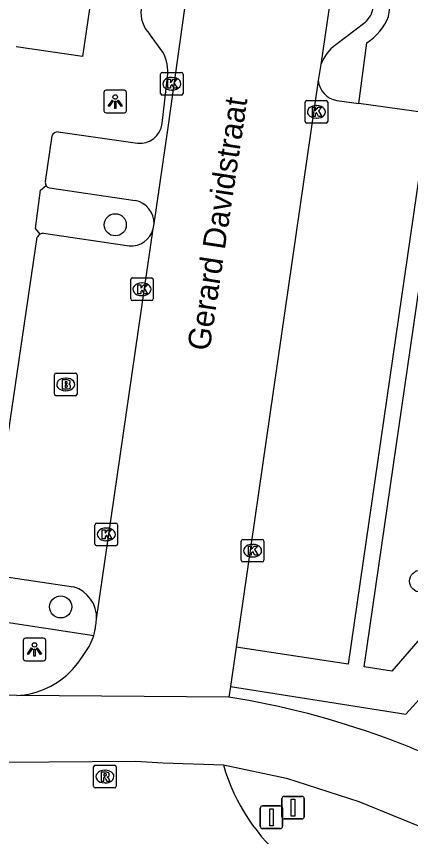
# Model space of a CAD drawing. Extents: x 163686 to 164493, y 382719 to 383870.
# Drawn here: x 163896.14 to 163913.6, y 382940.91 to 382977.2 of the extents above; entities that cross this region are included whole.
import ezdxf

# ---------------------------------------------------------------- set-up
doc = ezdxf.new("R2010")
doc.units = 0
for name, color, linetype in [('IMGEO_Boom', 7, 'Continuous'), ('IMGEO_Brandkraan', 7, 'Continuous'), ('IMGEO_Fietspad_gesloten', 7, 'Continuous'), ('IMGEO_Kolk', 7, 'Continuous'), ('IMGEO_Lichtpunt', 7, 'Continuous'), ('IMGEO_Openbare_ruimte_label', 7, 'Continuous'), ('IMGEO_Parkeervlak_open', 7, 'Continuous'), ('IMGEO_Rijbaan_lokaal_gesloten', 7, 'Continuous'), ('IMGEO_Rijbaan_lokaal_open', 7, 'Continuous'), ('IMGEO_Rioolput', 7, 'Continuous'), ('IMGEO_Verkeersbordpaal', 7, 'Continuous'), ('IMGEO_Voetpad_open', 7, 'Continuous')]:
    doc.layers.add(name, color=color, linetype=linetype)

msp = doc.modelspace()

# ---------------------------------------------------------------- linework, layer by layer
at = {"layer": 'IMGEO_Boom'}
for centre in [(163900.52, 382967.982), (163914.042, 382952.215), (163898.102, 382951.077)]:
    msp.add_circle(centre, 0.489, dxfattribs=at)
at = {"layer": 'IMGEO_Brandkraan'}
for p, q in [((163897.901, 382961.419), (163898.753, 382961.419)), ((163897.826, 382960.493), (163897.826, 382961.345)), ((163898.314, 382961.199), (163898.339, 382961.199)), ((163898.827, 382961.345), (163898.827, 382960.493)), ((163898.753, 382960.419), (163897.901, 382960.419)), ((163898.337, 382960.639), (163898.312, 382960.639))]:
    msp.add_line(p, q, dxfattribs=at)
for points in [[(163897.901, 382961.419), (163898.753, 382961.419)], [(163897.826, 382960.493), (163897.826, 382961.345)], [(163898.174, 382961.119), (163898.174, 382960.719), (163898.387, 382960.719)], [(163898.405, 382961.119), (163898.174, 382961.119)], [(163898.353, 382961.038), (163898.299, 382961.038), (163898.299, 382960.962)], [(163898.827, 382961.345), (163898.827, 382960.493)], [(163898.299, 382960.962), (163898.352, 382960.962)], [(163898.361, 382960.886), (163898.299, 382960.886), (163898.299, 382960.805)], [(163898.299, 382960.805), (163898.361, 382960.805)], [(163898.753, 382960.419), (163897.901, 382960.419)]]:
    msp.add_lwpolyline(points, dxfattribs=at)
for centre, radius, start, end in [((163897.903, 382961.343), 0.0765, 91.552, 178.448), ((163897.903, 382961.343), 0.0765, 91.552, 178.448), ((163898.751, 382961.343), 0.0765, 1.552, 88.448), ((163898.751, 382961.343), 0.0765, 1.552, 88.448), ((163898.354, 382961), 0.0379, 267.8285, 90.9355), ((163898.409, 382960.974), 0.145, 59.4692, 91.5367), ((163898.434, 382961.021), 0.0922, 285.5137, 58.1501), ((163898.362, 382960.845), 0.0404, 269.8759, 90.5077), ((163898.393, 382960.97), 0.251, 268.6676, 293.5347), ((163898.439, 382960.829), 0.105, 301.3115, 78.989), ((163897.903, 382960.495), 0.0765, 181.552, 268.448), ((163897.903, 382960.495), 0.0765, 181.552, 268.448), ((163898.751, 382960.495), 0.0765, 271.552, 358.448), ((163898.751, 382960.495), 0.0765, 271.552, 358.448)]:
    msp.add_arc(centre, radius, start, end, dxfattribs=at)
for centre, major_axis, ratio, start_param, end_param in [((163898.313, 382960.919), (-0.387, 0.002), 0.722429, 4.712389, 7.853982), ((163898.338, 382960.919), (-0.39, 0.002), 0.717154, 1.570796, 4.712389)]:
    msp.add_ellipse(centre, major_axis=major_axis, ratio=ratio, start_param=start_param, end_param=end_param, dxfattribs=at)
at = {"layer": 'IMGEO_Fietspad_gesloten'}
for points in [[(163896.153, 382947.159), (163892.166, 382947.287)], [(163905.31, 382944.094), (163908.103, 382943.494), (163911.308, 382942.464), (163918.914, 382939.372), (163922.003, 382938.314), (163925.083, 382937.398), (163927.264, 382936.845)]]:
    msp.add_lwpolyline(points, dxfattribs=at)
for centre, radius, start, end in [((163899.796, 382910.658), 36.873, 69.9359, 81.0113), ((163900.117, 382911.449), 36.02, 65.7637, 69.9836)]:
    msp.add_arc(centre, radius, start, end, dxfattribs=at)
at = {"layer": 'IMGEO_Kolk'}
for p, q in [((163902.526, 382973.797), (163902.526, 382974.649)), ((163902.601, 382974.723), (163903.453, 382974.723)), ((163903.014, 382974.503), (163903.039, 382974.503)), ((163903.527, 382974.649), (163903.527, 382973.797)), ((163903.453, 382973.723), (163902.601, 382973.723)), ((163903.037, 382973.943), (163903.012, 382973.943)), ((163908.929, 382972.555), (163908.929, 382973.407)), ((163909.004, 382973.481), (163909.856, 382973.481)), ((163909.93, 382973.407), (163909.93, 382972.555)), ((163909.417, 382973.261), (163909.442, 382973.261)), ((163909.44, 382972.701), (163909.415, 382972.701)), ((163909.856, 382972.481), (163909.004, 382972.481)), ((163901.204, 382964.705), (163901.204, 382965.557)), ((163901.279, 382965.631), (163902.131, 382965.631)), ((163901.692, 382965.411), (163901.717, 382965.411)), ((163902.205, 382965.557), (163902.205, 382964.705)), ((163901.715, 382964.851), (163901.69, 382964.851)), ((163902.131, 382964.631), (163901.279, 382964.631)), ((163899.622, 382953.859), (163899.622, 382954.711)), ((163899.697, 382954.785), (163900.549, 382954.785)), ((163900.11, 382954.565), (163900.135, 382954.565)), ((163900.623, 382954.711), (163900.623, 382953.859)), ((163900.549, 382953.785), (163899.697, 382953.785)), ((163900.133, 382954.005), (163900.108, 382954.005)), ((163906.102, 382953.138), (163906.102, 382953.99)), ((163906.177, 382954.064), (163907.029, 382954.064)), ((163906.59, 382953.844), (163906.615, 382953.844)), ((163907.103, 382953.99), (163907.103, 382953.138)), ((163907.029, 382953.064), (163906.177, 382953.064)), ((163906.613, 382953.284), (163906.588, 382953.284))]:
    msp.add_line(p, q, dxfattribs=at)
for points in [[(163902.526, 382973.797), (163902.526, 382974.649)], [(163902.601, 382974.723), (163903.453, 382974.723)], [(163903.527, 382974.649), (163903.527, 382973.797)], [(163902.847, 382974.423), (163902.97, 382974.423), (163902.97, 382974.272), (163903.1, 382974.423), (163903.264, 382974.423), (163903.118, 382974.272), (163903.271, 382974.023), (163903.119, 382974.023), (163903.034, 382974.187), (163902.97, 382974.12), (163902.97, 382974.023), (163902.847, 382974.023), (163902.847, 382974.423)], [(163903.453, 382973.723), (163902.601, 382973.723)], [(163908.929, 382972.555), (163908.929, 382973.407)], [(163909.004, 382973.481), (163909.856, 382973.481)], [(163909.93, 382973.407), (163909.93, 382972.555)], [(163909.25, 382973.181), (163909.373, 382973.181), (163909.373, 382973.03), (163909.503, 382973.181), (163909.667, 382973.181), (163909.521, 382973.03), (163909.674, 382972.781), (163909.522, 382972.781), (163909.437, 382972.945), (163909.373, 382972.878), (163909.373, 382972.781), (163909.25, 382972.781), (163909.25, 382973.181)], [(163909.856, 382972.481), (163909.004, 382972.481)], [(163901.204, 382964.705), (163901.204, 382965.557)], [(163901.279, 382965.631), (163902.131, 382965.631)], [(163902.205, 382965.557), (163902.205, 382964.705)], [(163901.525, 382965.331), (163901.648, 382965.331), (163901.648, 382965.18), (163901.778, 382965.331), (163901.942, 382965.331), (163901.796, 382965.18), (163901.949, 382964.931), (163901.797, 382964.931), (163901.712, 382965.095), (163901.648, 382965.028), (163901.648, 382964.931), (163901.525, 382964.931), (163901.525, 382965.331)], [(163902.131, 382964.631), (163901.279, 382964.631)], [(163899.622, 382953.859), (163899.622, 382954.711)], [(163899.697, 382954.785), (163900.549, 382954.785)], [(163899.943, 382954.485), (163900.066, 382954.485), (163900.066, 382954.334), (163900.196, 382954.485), (163900.36, 382954.485), (163900.214, 382954.334), (163900.367, 382954.085), (163900.215, 382954.085), (163900.13, 382954.249), (163900.066, 382954.182), (163900.066, 382954.085), (163899.943, 382954.085), (163899.943, 382954.485)], [(163900.623, 382954.711), (163900.623, 382953.859)], [(163900.549, 382953.785), (163899.697, 382953.785)], [(163906.102, 382953.138), (163906.102, 382953.99)], [(163906.177, 382954.064), (163907.029, 382954.064)], [(163906.423, 382953.764), (163906.546, 382953.764), (163906.546, 382953.613), (163906.676, 382953.764), (163906.84, 382953.764), (163906.694, 382953.613), (163906.847, 382953.364), (163906.695, 382953.364), (163906.61, 382953.528), (163906.546, 382953.461), (163906.546, 382953.364), (163906.423, 382953.364), (163906.423, 382953.764)], [(163907.103, 382953.99), (163907.103, 382953.138)], [(163907.029, 382953.064), (163906.177, 382953.064)]]:
    msp.add_lwpolyline(points, dxfattribs=at)
for centre, start, end in [((163902.603, 382974.647), 91.552, 178.448), ((163902.603, 382974.647), 91.552, 178.448), ((163903.451, 382974.647), 1.552, 88.448), ((163903.451, 382974.647), 1.552, 88.448), ((163902.603, 382973.799), 181.552, 268.448), ((163902.603, 382973.799), 181.552, 268.448), ((163903.451, 382973.799), 271.552, 358.448), ((163903.451, 382973.799), 271.552, 358.448), ((163909.006, 382973.405), 91.552, 178.448), ((163909.006, 382973.405), 91.552, 178.448), ((163909.854, 382973.405), 1.552, 88.448), ((163909.854, 382973.405), 1.552, 88.448), ((163909.006, 382972.557), 181.552, 268.448), ((163909.006, 382972.557), 181.552, 268.448), ((163909.854, 382972.557), 271.552, 358.448), ((163909.854, 382972.557), 271.552, 358.448), ((163901.281, 382965.555), 91.552, 178.448), ((163901.281, 382965.555), 91.552, 178.448), ((163902.129, 382965.555), 1.552, 88.448), ((163902.129, 382965.555), 1.552, 88.448), ((163901.281, 382964.707), 181.552, 268.448), ((163901.281, 382964.707), 181.552, 268.448), ((163902.129, 382964.707), 271.552, 358.448), ((163902.129, 382964.707), 271.552, 358.448), ((163899.699, 382954.709), 91.552, 178.448), ((163899.699, 382954.709), 91.552, 178.448), ((163900.547, 382954.709), 1.552, 88.448), ((163900.547, 382954.709), 1.552, 88.448), ((163899.699, 382953.861), 181.552, 268.448), ((163899.699, 382953.861), 181.552, 268.448), ((163900.547, 382953.861), 271.552, 358.448), ((163900.547, 382953.861), 271.552, 358.448), ((163906.179, 382953.988), 91.552, 178.448), ((163906.179, 382953.988), 91.552, 178.448), ((163907.027, 382953.988), 1.552, 88.448), ((163907.027, 382953.988), 1.552, 88.448), ((163906.179, 382953.14), 181.552, 268.448), ((163906.179, 382953.14), 181.552, 268.448), ((163907.027, 382953.14), 271.552, 358.448), ((163907.027, 382953.14), 271.552, 358.448)]:
    msp.add_arc(centre, 0.0765, start, end, dxfattribs=at)
for centre, major_axis, ratio, start_param, end_param in [((163903.013, 382974.223), (-0.387, 0.002), 0.722429, 4.712389, 7.853982), ((163903.038, 382974.223), (-0.39, 0.002), 0.717154, 1.570796, 4.712389), ((163909.416, 382972.981), (-0.387, 0.002), 0.722429, 4.712389, 7.853982), ((163909.441, 382972.981), (-0.39, 0.002), 0.717154, 1.570796, 4.712389), ((163901.691, 382965.131), (-0.387, 0.002), 0.722429, 4.712389, 7.853982), ((163901.716, 382965.131), (-0.39, 0.002), 0.717154, 1.570796, 4.712389), ((163900.109, 382954.285), (-0.387, 0.002), 0.722429, 4.712389, 7.853982), ((163900.134, 382954.285), (-0.39, 0.002), 0.717154, 1.570796, 4.712389), ((163906.589, 382953.564), (-0.387, 0.002), 0.722429, 4.712389, 7.853982), ((163906.614, 382953.564), (-0.39, 0.002), 0.717154, 1.570796, 4.712389)]:
    msp.add_ellipse(centre, major_axis=major_axis, ratio=ratio, start_param=start_param, end_param=end_param, dxfattribs=at)
at = {"layer": 'IMGEO_Lichtpunt'}
for p, q in [((163900.02, 382973.839), (163900.02, 382973.032)), ((163900.02, 382973.839), (163900.02, 382973.032)), ((163900.922, 382973.934), (163900.114, 382973.934)), ((163900.922, 382973.934), (163900.114, 382973.934)), ((163901.016, 382973.032), (163901.016, 382973.839)), ((163901.016, 382973.032), (163901.016, 382973.839)), ((163900.114, 382972.938), (163900.922, 382972.938)), ((163900.114, 382972.938), (163900.922, 382972.938)), ((163896.443, 382949.596), (163896.443, 382948.789)), ((163896.443, 382949.596), (163896.443, 382948.789)), ((163897.345, 382949.691), (163896.537, 382949.691)), ((163897.345, 382949.691), (163896.537, 382949.691)), ((163897.439, 382948.789), (163897.439, 382949.596)), ((163897.439, 382948.789), (163897.439, 382949.596)), ((163896.537, 382948.695), (163897.345, 382948.695)), ((163896.537, 382948.695), (163897.345, 382948.695))]:
    msp.add_line(p, q, dxfattribs=at)
for points in [[(163900.394, 382973.503), (163900.433, 382973.475), (163900.245, 382973.213), (163900.207, 382973.24), (163900.394, 382973.503)], [(163900.496, 382973.455), (163900.543, 382973.455), (163900.543, 382973.133), (163900.496, 382973.133), (163900.496, 382973.455)], [(163900.606, 382973.475), (163900.644, 382973.502), (163900.831, 382973.24), (163900.792, 382973.212), (163900.606, 382973.475)], [(163896.817, 382949.26), (163896.856, 382949.232), (163896.668, 382948.97), (163896.63, 382948.997), (163896.817, 382949.26)], [(163896.919, 382949.212), (163896.966, 382949.212), (163896.966, 382948.89), (163896.919, 382948.89), (163896.919, 382949.212)], [(163897.029, 382949.232), (163897.067, 382949.259), (163897.254, 382948.997), (163897.215, 382948.969), (163897.029, 382949.232)]]:
    msp.add_lwpolyline(points, dxfattribs=at)
for centre in [(163900.519, 382973.637), (163896.942, 382949.394)]:
    msp.add_circle(centre, 0.0994, dxfattribs=at)
for centre, start, end in [((163900.114, 382973.839), 90, 180), ((163900.114, 382973.839), 90, 180), ((163900.922, 382973.839), 0, 90), ((163900.922, 382973.839), 0, 90), ((163900.114, 382973.032), 180, 270), ((163900.114, 382973.032), 180, 270), ((163900.922, 382973.032), 270, 0), ((163900.922, 382973.032), 270, 360), ((163896.537, 382949.596), 90, 180), ((163896.537, 382949.596), 90, 180), ((163897.345, 382949.596), 0, 90), ((163897.345, 382949.596), 0, 90), ((163896.537, 382948.789), 180, 270), ((163896.537, 382948.789), 180, 270), ((163897.345, 382948.789), 270, 0), ((163897.345, 382948.789), 270, 360)]:
    msp.add_arc(centre, 0.0946, start, end, dxfattribs=at)
at = {"layer": 'IMGEO_Parkeervlak_open'}
for points in [[(163914.373, 382972.917), (163911.306, 382973.343)], [(163897.605, 382969.616), (163901.396, 382969.058)], [(163897.343, 382967.607), (163901.134, 382967.05)], [(163895.078, 382952.495), (163898.674, 382951.965)]]:
    msp.add_lwpolyline(points, dxfattribs=at)
for centre, radius, start, end in [((163897.655, 382969.843), 0.233, 209.6931, 257.5382), ((163901.225, 382968.058), 1.014, 357.7736, 80.2686), ((163897.337, 382967.32), 0.287, 88.7231, 120.2405), ((163901.225, 382968.059), 1.013, 264.8221, 345.09), ((163898.26, 382950.591), 1.435, 357.5352, 73.2377)]:
    msp.add_arc(centre, radius, start, end, dxfattribs=at)
at = {"layer": 'IMGEO_Rijbaan_lokaal_gesloten'}
msp.add_lwpolyline([(163895.665, 382944.21), (163901.419, 382944.25), (163902.648, 382944.184), (163905.31, 382944.094)], dxfattribs=at)
msp.add_arc((163913.567, 382946.445), 8.586, 195.8916, 266.0232, dxfattribs=at)
at = {"layer": 'IMGEO_Rijbaan_lokaal_open'}
for points in [[(163918.053, 383032.612), (163909.629, 382975.079)], [(163902.238, 382968.019), (163902.885, 382972.393), (163904.727, 382985.584)], [(163909.629, 382975.079), (163909.513, 382974.371)], [(163909.513, 382974.371), (163905.868, 382949.288)], [(163902.204, 382967.798), (163902.238, 382968.019)], [(163899.694, 382950.529), (163902.204, 382967.798)], [(163899.652, 382950.24), (163899.694, 382950.529)], [(163898.628, 382948.311), (163898.859, 382948.591), (163899.032, 382948.844), (163899.187, 382949.054)], [(163905.868, 382949.288), (163905.621, 382947.552)], [(163905.621, 382947.552), (163905.557, 382947.078)], [(163905.557, 382947.078), (163896.153, 382947.159)]]:
    msp.add_lwpolyline(points, dxfattribs=at)
for centre, radius, start, end in [((163897.275, 382950.499), 2.391, 343.4468, 353.7767), ((163897.198, 382950.52), 2.471, 323.6107, 343.4995), ((163895.998, 382950.727), 3.572, 272.4906, 317.4291)]:
    msp.add_arc(centre, radius, start, end, dxfattribs=at)
at = {"layer": 'IMGEO_Rioolput'}
for p, q in [((163899.56, 382943.143), (163899.56, 382943.995)), ((163899.635, 382944.069), (163900.487, 382944.069)), ((163900.561, 382943.995), (163900.561, 382943.143)), ((163900.048, 382943.849), (163900.073, 382943.849)), ((163900.071, 382943.289), (163900.046, 382943.289)), ((163900.487, 382943.069), (163899.635, 382943.069))]:
    msp.add_line(p, q, dxfattribs=at)
for points in [[(163899.56, 382943.143), (163899.56, 382943.995)], [(163899.635, 382944.069), (163900.487, 382944.069)], [(163900.561, 382943.995), (163900.561, 382943.143)], [(163900.149, 382943.767), (163899.897, 382943.769), (163899.897, 382943.369)], [(163900.075, 382943.688), (163900.021, 382943.688), (163900.021, 382943.607)], [(163900.021, 382943.607), (163900.073, 382943.607)], [(163899.897, 382943.369), (163900.021, 382943.369), (163900.021, 382943.531), (163900.032, 382943.531)], [(163900.079, 382943.502), (163900.15, 382943.369), (163900.29, 382943.369), (163900.225, 382943.495)], [(163900.487, 382943.069), (163899.635, 382943.069)]]:
    msp.add_lwpolyline(points, dxfattribs=at)
for centre, radius, start, end in [((163899.637, 382943.993), 0.0765, 91.552, 178.448), ((163899.637, 382943.993), 0.0765, 91.552, 178.448), ((163900.485, 382943.993), 0.0765, 1.552, 88.448), ((163900.485, 382943.993), 0.0765, 1.552, 88.448), ((163900.057, 382943.796), 0.19, 274.7715, 282.9687), ((163900.081, 382943.592), 0.0964, 77.0061, 93.1865), ((163900.095, 382943.649), 0.0378, 276.6634, 79.6772), ((163900.148, 382943.657), 0.109, 350.3612, 89.416), ((163900.146, 382943.657), 0.112, 277.5842, 350.9817), ((163900.031, 382943.478), 0.0533, 26.0293, 88.6989), ((163900.13, 382943.442), 0.108, 29.5134, 73.7905), ((163899.637, 382943.145), 0.0765, 181.552, 268.448), ((163899.637, 382943.145), 0.0765, 181.552, 268.448), ((163900.485, 382943.145), 0.0765, 271.552, 358.448), ((163900.485, 382943.145), 0.0765, 271.552, 358.448)]:
    msp.add_arc(centre, radius, start, end, dxfattribs=at)
for centre, major_axis, ratio, start_param, end_param in [((163900.047, 382943.569), (-0.387, 0.002), 0.722429, 4.712389, 7.853982), ((163900.072, 382943.569), (-0.39, 0.002), 0.717154, 1.570796, 4.712389)]:
    msp.add_ellipse(centre, major_axis=major_axis, ratio=ratio, start_param=start_param, end_param=end_param, dxfattribs=at)
at = {"layer": 'IMGEO_Verkeersbordpaal'}
for p, q in [((163907.898, 382941.794), (163907.898, 382942.594)), ((163907.898, 382942.594), (163907.898, 382941.794)), ((163907.998, 382942.694), (163908.788, 382942.694)), ((163908.788, 382942.694), (163907.998, 382942.694)), ((163908.888, 382942.594), (163908.888, 382941.794)), ((163908.888, 382941.794), (163908.888, 382942.594)), ((163906.94, 382941.37), (163906.94, 382942.17)), ((163906.94, 382942.17), (163906.94, 382941.37)), ((163907.04, 382942.27), (163907.83, 382942.27)), ((163907.83, 382942.27), (163907.04, 382942.27)), ((163907.93, 382942.17), (163907.93, 382941.37)), ((163907.93, 382941.37), (163907.93, 382942.17)), ((163908.788, 382941.694), (163907.998, 382941.694)), ((163907.998, 382941.694), (163908.788, 382941.694)), ((163907.83, 382941.27), (163907.04, 382941.27)), ((163907.04, 382941.27), (163907.83, 382941.27))]:
    msp.add_line(p, q, dxfattribs=at)
for points in [[(163908.318, 382942.569), (163908.468, 382942.569), (163908.468, 382941.819), (163908.318, 382941.819), (163908.318, 382942.569)], [(163907.36, 382942.145), (163907.51, 382942.145), (163907.51, 382941.395), (163907.36, 382941.395), (163907.36, 382942.145)]]:
    msp.add_lwpolyline(points, dxfattribs=at)
for centre, start, end in [((163907.998, 382942.594), 90, 180), ((163907.998, 382942.594), 90, 180), ((163908.788, 382942.594), 0, 90), ((163908.788, 382942.594), 360, 90), ((163907.04, 382942.17), 90, 180), ((163907.04, 382942.17), 90, 180), ((163907.83, 382942.17), 0, 90), ((163907.83, 382942.17), 360, 90), ((163907.998, 382941.794), 180, 270), ((163907.998, 382941.794), 180, 270), ((163908.788, 382941.794), 270, 0), ((163908.788, 382941.794), 270, 0), ((163907.04, 382941.37), 180, 270), ((163907.04, 382941.37), 180, 270), ((163907.83, 382941.37), 270, 0), ((163907.83, 382941.37), 270, 0)]:
    msp.add_arc(centre, 0.1, start, end, dxfattribs=at)
at = {"layer": 'IMGEO_Voetpad_open'}
for points in [[(163909.586, 383046.915), (163899.064, 382975.425), (163896.128, 382975.857)], [(163912.626, 382977.201), (163914.464, 382989.496), (163918.521, 382988.903)], [(163911.572, 382976.924), (163910.287, 382975.949)], [(163902.633, 382975.621), (163902.033, 382976.437)], [(163911.306, 382973.343), (163911.665, 382976.038)], [(163902.59, 382972.459), (163902.837, 382974.529)], [(163910.335, 382973.479), (163911.306, 382973.343)], [(163914.373, 382972.917), (163910.833, 382948.544), (163905.868, 382949.288)], [(163897.426, 382969.894), (163897.72, 382971.921)], [(163897.987, 382972.094), (163901.506, 382971.591)], [(163897.192, 382967.568), (163896.986, 382967.823), (163897.213, 382969.515), (163897.453, 382969.728)], [(163894.887, 382952.759), (163897.067, 382967.43)], [(163919.168, 382963.525), (163917.758, 382953.979), (163912.77, 382948.231), (163911.547, 382948.427), (163913.998, 382965.282), (163918.31, 382964.671)], [(163905.621, 382947.552), (163913.391, 382946.329), (163915.475, 382948.612), (163919.234, 382953.124)], [(163894.432, 382950.591), (163899.567, 382949.818)]]:
    msp.add_lwpolyline(points, dxfattribs=at)
for centre, radius, start, end in [((163903.023, 382977.381), 1.368, 173.5994, 223.6152), ((163910.832, 382977.765), 1.12, 311.3314, 352.1961), ((163910.307, 382978.139), 2.501, 302.8814, 337.984), ((163911.383, 382974.436), 1.868, 125.9218, 159.8762), ((163901.024, 382974.755), 1.827, 352.8799, 28.2834), ((163910.508, 382974.463), 0.999, 185.27, 260.0527), ((163901.614, 382972.567), 0.982, 263.6961, 353.675), ((163897.966, 382971.833), 0.261, 85.4479, 160.4338), ((163897.655, 382969.846), 0.234, 168.1918, 210.2848), ((163897.335, 382967.313), 0.292, 119.2401, 156.4195)]:
    msp.add_arc(centre, radius, start, end, dxfattribs=at)

# ---------------------------------------------------------------- texts
at = {"layer": 'IMGEO_Openbare_ruimte_label'}
msp.add_text('Gerard Davidstraat', height=1, rotation=81.4324, dxfattribs=at).set_placement((163904.693, 382962.37))

doc.saveas('drawing.dxf')
